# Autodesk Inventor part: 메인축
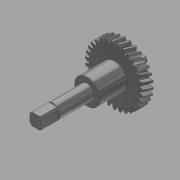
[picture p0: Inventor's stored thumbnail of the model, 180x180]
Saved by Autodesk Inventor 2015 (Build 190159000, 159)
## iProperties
Created: 2017-11
Part Number: 메인축
Material: 강철, 탄소
Document SubType Name: Modeling
Designer: mduedu
Categories: <?xml version="1.0" encoding="UTF-16"?> <MemberInstance><Categories><FamilyTemplate><FamilyTemplateParameter ValueType="xs:double" Id="1" ObjectReferenceKey="da
Density: 7.87 g/cm^3
Mass: 607.365 g
Surface Area: 183.17 cm^2
Volume: 77.1747 cm^3
Appearance: 반광택
CustomPartVersion: 1
Author: mduedu
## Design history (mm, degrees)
sketch "Sketch1"
  geometry: C1 r 34.094 at (0, 0)
  constraints: 1 centre point
  dimensions: "d0" = 68.18712 diameter of C1 (= da_da)
extrude "Extrusion1" new body sketch "Sketch1" distance "d1" = 12 (= da_b); taper "d2" = 0 deg
workplane "Work Plane2"
sketch "Sketch2"
  geometry: C1 r 34.094 at (0, 0) reference; C2 r 32.094 at (0, 0)
  constraints: 1 centre point, 1 coincident
  dimensions: "d3" = 64.18712 diameter of C2 (= da_dw)
feature "피치 지름" sketch "Sketch2" dims "d4" = 10, "d5" = 0
workplane "Work Plane8"
workplane "Work Plane9"
feature "스퍼 기어" dims "da_b" = 12, "da_d" = 64.18712, "da_aw" = 54.86964, "da_da" = 68.18712, "da_df" = 59.18712, "da_dw" = 64.18712, angle "da_beta" = 15 deg, "da_lefttooth" = 0, "da_righttooth" = 10
sketch "스케치3"
  geometry: C1 r 15 at (0, 0); 1 further point
  constraints: 1 centre point, 1 coincident
  dimensions: "d49" = 30 diameter of C1
extrude "돌출2" join sketch "스케치3" distance "d50" = 32; taper "d51" = 0 deg
sketch "스케치4"
  geometry: C1 r 8.5 at (0, 0); 1 further point
  constraints: 1 centre point, 1 coincident
  dimensions: "d52" = 17 diameter of C1
extrude "돌출3" join sketch "스케치4" distance "d53" = 60; taper "d54" = 0 deg
sketch "스케치5"
  geometry: C1 r 7.5 at (0, 0); 1 further point
  constraints: 1 centre point, 1 coincident
  dimensions: "d55" = 15 diameter of C1
extrude "돌출4" join sketch "스케치5" distance "d56" = 16; taper "d57" = 0 deg
sketch "스케치6"
  geometry: C1 r 4 at (0, 0); 1 further point
  constraints: 1 centre point, 1 coincident
  dimensions: "d58" = 8 diameter of C1
extrude "돌출5" join sketch "스케치6" distance "d59" = 7; taper "d60" = 0 deg
chamfer "모따기1" distance "d61" = 0.5; stored, may be unused: second distance "d62" = 2, angle "d63" = 45 deg
fillet "모깎기1" dims "d64" = 0.5
sketch "스케치7"
  geometry: L1 (-7, -7)-(7, -7); L2 (7, -7)-(7, 7); L3 (7, 7)-(-7, 7); L4 (-7, 7)-(-7, -7); L5 (-7, -7)-(7, 7); L6 (7, -7)-(-7, 7); L7 (-10, -10)-(10, -10); L8 (10, -10)-(10, 10); L9 (10, 10)-(-10, 10); L10 (-10, 10)-(-10, -10); L11 (-10, -10)-(10, 10); L12 (10, -10)-(-10, 10); 1 further point
  constraints: 24 end point, 4 midpoint, 4 parallel, 2 horizontal, 2 perpendicular
  dimensions: "d65" = 14 distance of L3.end L2.end; "d66" = 14 distance of L2.end L1.end; "d67" = 20 distance of L9.end L8.end; "d68" = 20 distance of L8.end L7.end
extrude "돌출6" cut sketch "스케치7" distance "d69" = 20; taper "d70" = 0 deg
body "Solid1"
body "Srf1"
other parameters: "d16" = 54.86964 (= da_aw), "d17" = 0, "d34" = 1.01342 (computed from da_z), "d39" = 0, "d41" = 0, "d43" = 54.86964 (= da_aw), "d46" = 54.86964 (= da_aw), "d47" = 0, "d48" = 0
